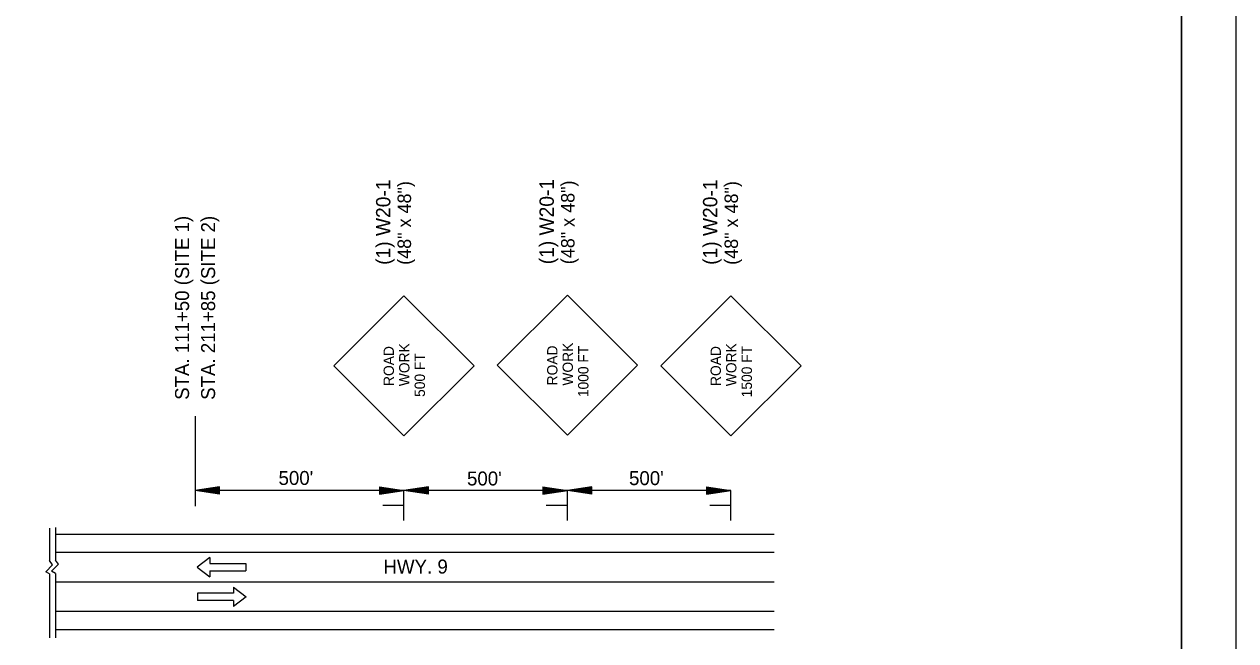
# Model space of a CAD drawing. Extents: x 1398460 to 1408037, y 380768 to 383968.
# Drawn here: x 1403470 to 1403999, y 383428 to 383698 of the extents above; entities that cross this region are included whole.
import ezdxf

# ---------------------------------------------------------------- set-up
doc = ezdxf.new("R2010")
doc.units = 0
for name, color, linetype in [('Default', 7, 'Continuous'), ('R_Border', 7, 'Continuous'), ('R_Dimension', 7, 'Continuous'), ('R_Draft', 7, 'Continuous'), ('R_MOT', 7, 'Continuous'), ('R_No Plot', 7, 'Continuous')]:
    doc.layers.add(name, color=color, linetype=linetype)

msp = doc.modelspace()

# ---------------------------------------------------------------- linework, layer by layer
at = {"layer": 'Default'}
for p, q in [((1403544.22, 383526.48), (1403544.22, 383487.19)), ((1403635.47, 383494.03), (1403544.22, 383494.03)), ((1403706.9, 383494.03), (1403635.47, 383494.03)), ((1403778.33, 383494.03), (1403706.9, 383494.03)), ((1403480.61, 383477.57), (1403480.61, 383463.36)), ((1403483.19, 383477.75), (1403483.19, 383463.54)), ((1403797.19, 383466.8), (1403483.19, 383466.8)), ((1403550.65, 383464.74), (1403545.09, 383460.45)), ((1403550.65, 383464.74), (1403550.65, 383462.06)), ((1403545.09, 383460.45), (1403550.65, 383456.17)), ((1403550.65, 383462.06), (1403566.41, 383462.06)), ((1403550.65, 383458.84), (1403566.41, 383458.84)), ((1403550.65, 383458.84), (1403550.65, 383456.17)), ((1403566.41, 383462.06), (1403566.41, 383458.84)), ((1403480.61, 383457.48), (1403480.61, 383429.6)), ((1403483.19, 383457.67), (1403483.19, 383429.6)), ((1403797.19, 383453.94), (1403483.19, 383453.94)), ((1403561.01, 383449.09), (1403545.25, 383449.09)), ((1403545.25, 383449.09), (1403545.25, 383445.88)), ((1403561.01, 383451.77), (1403561.01, 383449.09)), ((1403561.01, 383451.77), (1403566.57, 383447.48)), ((1403561.01, 383445.88), (1403545.25, 383445.88)), ((1403566.57, 383447.48), (1403561.01, 383443.2)), ((1403561.01, 383445.88), (1403561.01, 383443.2)), ((1403797.19, 383441.08), (1403483.19, 383441.08))]:
    msp.add_line(p, q, dxfattribs=at)
for points in [[(1403480.61, 383457.48), (1403478.96, 383458.47), (1403481.91, 383461.51), (1403480.61, 383463.36)], [(1403483.19, 383457.67), (1403481.54, 383458.65), (1403484.49, 383461.7), (1403483.19, 383463.54)]]:
    msp.add_lwpolyline(points, dxfattribs=at)
at = {"layer": 'R_Border'}
msp.add_line((1403975.17, 382920.81), (1403975.17, 383948.11), dxfattribs=at)
at = {"layer": 'R_Dimension'}
for p, q in [((1403797.19, 383474.8), (1403483.19, 383474.8)), ((1403797.19, 383433.08), (1403483.19, 383433.08))]:
    msp.add_line(p, q, dxfattribs=at)
at = {"layer": 'R_Draft'}
for p, q in [((1403554.93, 383495.64), (1403544.22, 383494.03)), ((1403554.93, 383492.43), (1403544.22, 383494.03)), ((1403554.93, 383495.37), (1403546, 383494.03)), ((1403554.93, 383492.69), (1403546, 383494.03)), ((1403554.93, 383495.1), (1403547.85, 383494.03)), ((1403554.93, 383492.97), (1403547.85, 383494.03)), ((1403554.93, 383494.83), (1403549.63, 383494.03)), ((1403554.93, 383493.24), (1403549.63, 383494.03)), ((1403554.93, 383494.56), (1403551.45, 383494.03)), ((1403554.93, 383493.51), (1403551.45, 383494.03)), ((1403554.93, 383494.29), (1403553.24, 383494.03)), ((1403554.93, 383493.78), (1403553.24, 383494.03)), ((1403554.93, 383492.43), (1403554.93, 383495.64)), ((1403624.76, 383495.64), (1403635.47, 383494.03)), ((1403624.76, 383495.64), (1403624.76, 383492.43)), ((1403624.76, 383495.37), (1403633.68, 383494.03)), ((1403624.76, 383495.1), (1403631.84, 383494.03)), ((1403624.76, 383494.83), (1403630.06, 383494.03)), ((1403624.76, 383494.55), (1403628.24, 383494.03)), ((1403624.76, 383494.29), (1403626.45, 383494.03)), ((1403624.76, 383492.43), (1403635.47, 383494.03)), ((1403624.76, 383493.51), (1403628.24, 383494.03)), ((1403624.76, 383492.97), (1403631.84, 383494.03)), ((1403624.76, 383492.69), (1403633.68, 383494.03)), ((1403624.76, 383493.24), (1403630.06, 383494.03)), ((1403624.76, 383493.78), (1403626.45, 383494.03)), ((1403646.19, 383495.64), (1403635.47, 383494.03)), ((1403646.19, 383492.43), (1403635.47, 383494.03)), ((1403646.19, 383495.37), (1403637.26, 383494.03)), ((1403646.19, 383492.69), (1403637.26, 383494.03)), ((1403646.19, 383495.1), (1403639.1, 383494.03)), ((1403646.19, 383492.97), (1403639.1, 383494.03)), ((1403646.19, 383494.83), (1403640.89, 383494.03)), ((1403646.19, 383493.24), (1403640.89, 383494.03)), ((1403646.19, 383494.56), (1403642.7, 383494.03)), ((1403646.19, 383493.51), (1403642.7, 383494.03)), ((1403646.19, 383494.29), (1403644.49, 383494.03)), ((1403646.19, 383493.78), (1403644.49, 383494.03)), ((1403646.19, 383492.43), (1403646.19, 383495.64)), ((1403696.19, 383495.64), (1403706.9, 383494.03)), ((1403696.19, 383495.64), (1403696.19, 383492.43)), ((1403696.19, 383495.37), (1403705.11, 383494.03)), ((1403696.19, 383495.1), (1403703.27, 383494.03)), ((1403696.19, 383494.83), (1403701.48, 383494.03)), ((1403696.19, 383494.55), (1403699.67, 383494.03)), ((1403696.19, 383494.29), (1403697.88, 383494.03)), ((1403696.19, 383492.43), (1403706.9, 383494.03)), ((1403696.19, 383493.51), (1403699.67, 383494.03)), ((1403696.19, 383492.97), (1403703.27, 383494.03)), ((1403696.19, 383492.69), (1403705.11, 383494.03)), ((1403696.19, 383493.24), (1403701.48, 383494.03)), ((1403696.19, 383493.78), (1403697.88, 383494.03)), ((1403717.61, 383495.64), (1403706.9, 383494.03)), ((1403717.61, 383492.43), (1403706.9, 383494.03)), ((1403717.61, 383495.37), (1403708.69, 383494.03)), ((1403717.61, 383492.69), (1403708.69, 383494.03)), ((1403717.61, 383495.1), (1403710.53, 383494.03)), ((1403717.61, 383492.97), (1403710.53, 383494.03)), ((1403717.61, 383494.83), (1403712.32, 383494.03)), ((1403717.61, 383493.24), (1403712.32, 383494.03)), ((1403717.61, 383494.56), (1403714.13, 383494.03)), ((1403717.61, 383493.51), (1403714.13, 383494.03)), ((1403717.61, 383494.29), (1403715.92, 383494.03)), ((1403717.61, 383493.78), (1403715.92, 383494.03)), ((1403717.61, 383492.43), (1403717.61, 383495.64)), ((1403767.61, 383495.64), (1403778.33, 383494.03)), ((1403767.61, 383495.64), (1403767.61, 383492.43)), ((1403767.61, 383495.37), (1403776.54, 383494.03)), ((1403767.61, 383495.1), (1403774.7, 383494.03)), ((1403767.61, 383494.83), (1403772.91, 383494.03)), ((1403767.61, 383494.55), (1403771.1, 383494.03)), ((1403767.61, 383494.29), (1403769.31, 383494.03)), ((1403767.61, 383492.43), (1403778.33, 383494.03)), ((1403767.61, 383493.51), (1403771.1, 383494.03)), ((1403767.61, 383492.97), (1403774.7, 383494.03)), ((1403767.61, 383492.69), (1403776.54, 383494.03)), ((1403767.61, 383493.24), (1403772.91, 383494.03)), ((1403767.61, 383493.78), (1403769.31, 383494.03))]:
    msp.add_line(p, q, dxfattribs=at)
at = {"layer": 'R_MOT'}
for p, q in [((1403635.47, 383579.19), (1403604.82, 383548.54)), ((1403635.47, 383579.19), (1403666.1, 383548.54)), ((1403706.9, 383579.45), (1403676.25, 383548.81)), ((1403706.9, 383579.45), (1403737.53, 383548.81)), ((1403778.33, 383579.19), (1403747.68, 383548.54)), ((1403778.33, 383579.19), (1403808.96, 383548.54)), ((1403676.25, 383548.81), (1403706.9, 383518.16)), ((1403737.53, 383548.81), (1403706.9, 383518.16)), ((1403604.82, 383548.54), (1403635.47, 383517.89)), ((1403666.1, 383548.54), (1403635.47, 383517.89)), ((1403747.68, 383548.54), (1403778.33, 383517.89)), ((1403808.96, 383548.54), (1403778.33, 383517.89)), ((1403635.47, 383480.8), (1403635.47, 383494.03)), ((1403706.9, 383480.8), (1403706.9, 383494.03)), ((1403778.33, 383480.8), (1403778.33, 383494.03)), ((1403635.28, 383487.38), (1403626.24, 383487.38)), ((1403706.71, 383487.38), (1403697.67, 383487.38)), ((1403778.14, 383487.38), (1403769.1, 383487.38))]:
    msp.add_line(p, q, dxfattribs=at)
at = {"layer": 'R_No Plot'}
for points in [[(1402332.23, 383967.58), (1403998.93, 383967.58), (1403998.93, 382900.89), (1402332.23, 382900.89)], [(1403563.87, 383948.11), (1403661.97, 383948.11), (1403661.97, 383898.71), (1403742.53, 383898.71), (1403858.52, 383898.71), (1403858.52, 383777.04), (1403975.17, 383777.04), (1403975.17, 382920.81), (1402394.27, 382920.81), (1402394.27, 383948.11)]]:
    msp.add_lwpolyline(points, close=True, dxfattribs=at)

# ---------------------------------------------------------------- texts
at = {"layer": 'Default'}
for s, rotation, p in [('STA. 111+50 (SITE 1)', 90, (1403541.57, 383533.62)), ('STA. 211+85 (SITE 2)', 90, (1403552.96, 383533.62)), ("500'", 360, (1403580.67, 383496.41)), ("500'", 360, (1403663.02, 383496.18)), ("500'", 360, (1403733.81, 383496.34)), ('HWY. 9', 0.19, (1403626.54, 383457.58))]:
    msp.add_text(s, height=6.1, rotation=rotation, dxfattribs=at).set_placement(p)
at = {"layer": 'R_MOT'}
for s, height, rotation, p in [('(1) W20-1', 6.273, 90, (1403629.54, 383592.68)), ('(48" x 48")', 5.88, 90, (1403638.57, 383592.68)), ('(1) W20-1', 6.273, 90, (1403700.97, 383592.94)), ('(48" x 48")', 5.88, 90, (1403710, 383592.94)), ('(1) W20-1', 6.273, 90, (1403772.4, 383592.68)), ('(48" x 48")', 5.88, 90, (1403781.43, 383592.68)), ('ROAD', 4.516, 90.0004, (1403631.1, 383539.69)), ('WORK', 4.515, 90, (1403637.88, 383539.6)), ('ROAD', 4.516, 90.0004, (1403702.54, 383539.95)), ('WORK', 4.515, 90, (1403709.31, 383539.86)), ('1000 FT', 4.516, 90.0006, (1403716.08, 383534.81)), ('ROAD', 4.516, 90.0004, (1403773.96, 383539.69)), ('WORK', 4.515, 90, (1403780.74, 383539.6)), ('1500 FT', 4.516, 90.0006, (1403787.52, 383534.73)), (' 500 FT', 4.516, 90.0006, (1403644.65, 383533.22))]:
    msp.add_text(s, height=height, rotation=rotation, dxfattribs=at).set_placement(p)

doc.saveas('drawing.dxf')
